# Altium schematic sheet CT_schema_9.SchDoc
size 254 x 194 mm
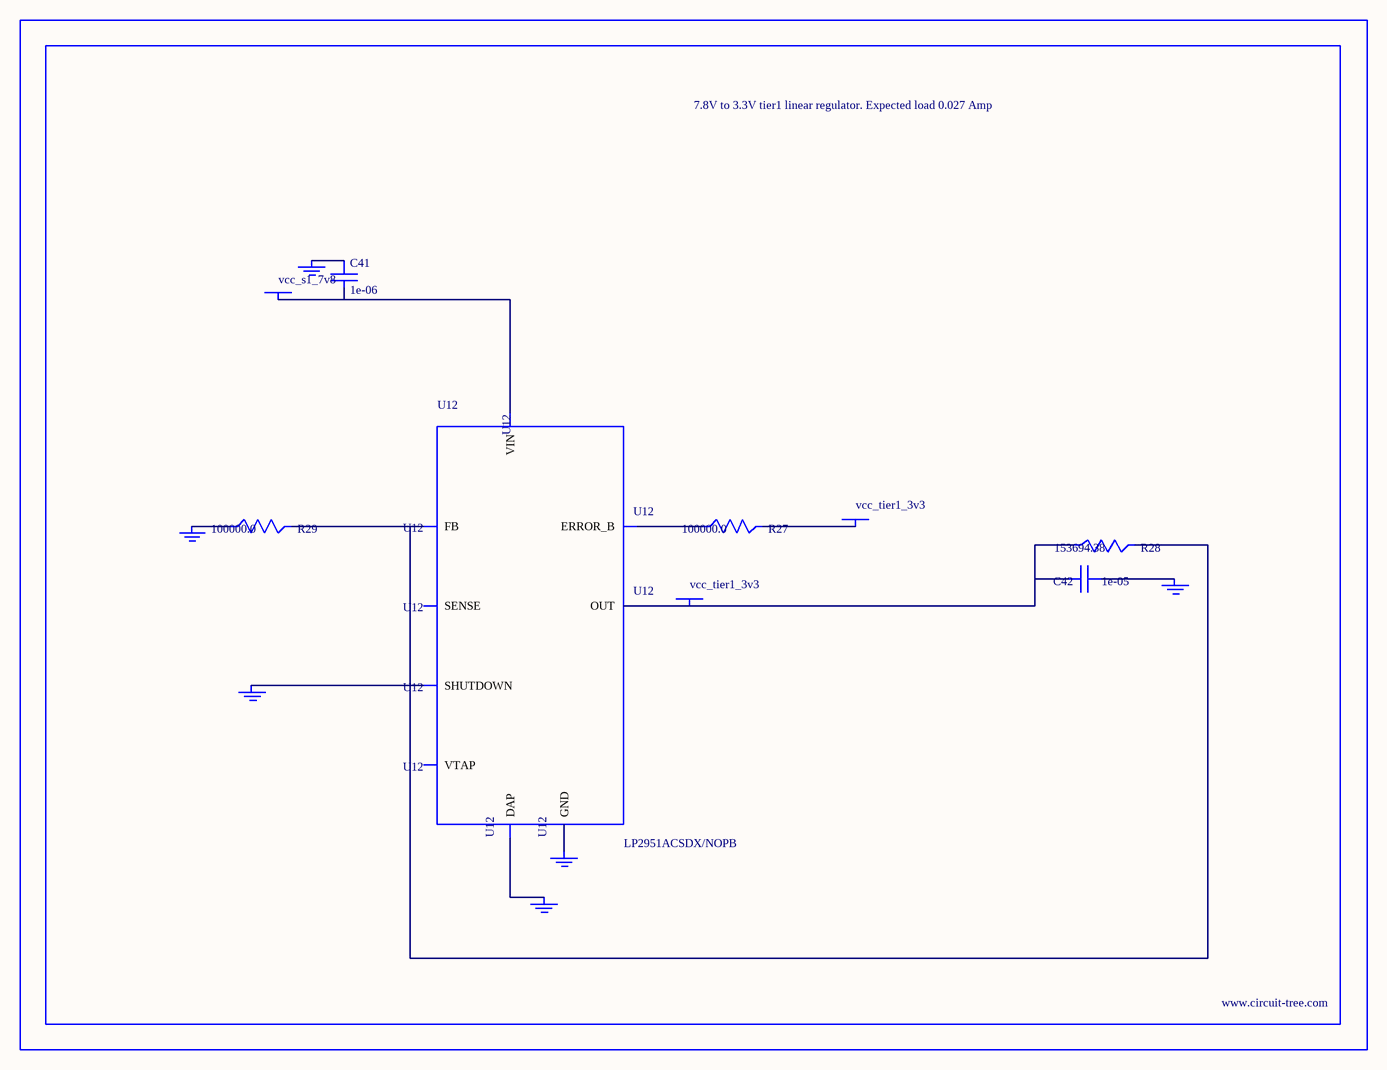
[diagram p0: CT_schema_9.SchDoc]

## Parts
BORDER8  (no value)
C41  1e-06  [C0603]
C42  1e-05  [C1210]
GND_INSTANCE_8_0  (no value)
GND_INSTANCE_8_1  (no value)
GND_INSTANCE_8_2  (no value)
GND_INSTANCE_8_3  (no value)
GND_INSTANCE_8_4  (no value)
GND_INSTANCE_8_5  (no value)
POWER_INSTANCE_8_0  vcc_tier1_3v3
POWER_INSTANCE_8_1  vcc_s1_7v8
POWER_INSTANCE_8_2  vcc_tier1_3v3
R27  100000.0  [R0603]
R28  153694.38  [R0603]
R29  100000.0  [R0603]
U12  LP2951ACSDX/NOPB  [WSON-8]

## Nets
NetC41_1: C41.1 GND_INSTANCE_8_3.0(GND)
NetC41_2: C41.2 POWER_INSTANCE_8_1.0(PWR) U12.8(VIN)
NetC42_1: C42.1 GND_INSTANCE_8_0.0(GND)
NetC42_2: C42.2 POWER_INSTANCE_8_2.0(PWR) R28.1 U12.1(OUT)
NetGND_INSTANCE_8_1_0: GND_INSTANCE_8_1.0(GND) U12.3(SHUTDOWN)
NetGND_INSTANCE_8_2_0: GND_INSTANCE_8_2.0(GND) R29.1
NetGND_INSTANCE_8_4_0: GND_INSTANCE_8_4.0(GND) U12.PAD(DAP)
NetGND_INSTANCE_8_5_0: GND_INSTANCE_8_5.0(GND) U12.4(GND)
NetPOWER_INSTANCE_8_0_0: POWER_INSTANCE_8_0.0(PWR) R27.2
NetR27_1: R27.1 U12.5(ERROR_B)
NetR28_2: R28.2 R29.2 U12.7(FB)

Not connected (* = marked no-connect by the designer): U12 2(SENSE) 6(VTAP)

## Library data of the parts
BORDER8 = BORDER_PAGE8
C41 = C0603C105K3RACTU
C42 = GRM32DR61E106MA12L
GND_INSTANCE_8_0-GND_INSTANCE_8_5 = GND
POWER_INSTANCE_8_0-POWER_INSTANCE_8_2 = PWR
R27 R29 = RC0603JR-07100KL
R28 = R28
